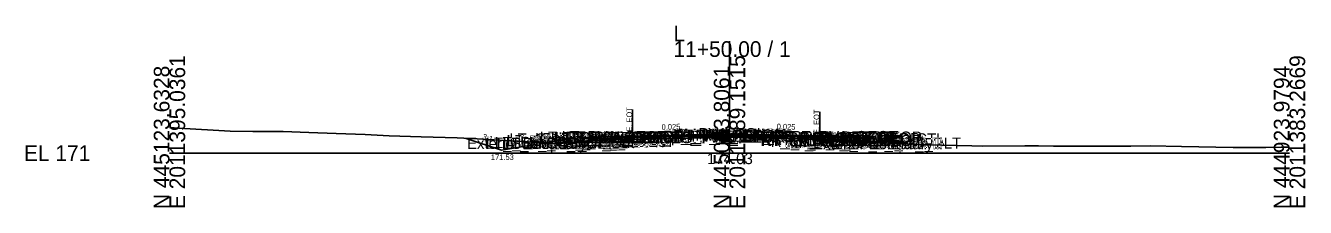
# Model space of a CAD drawing. Extents: x -26 to 4203, y -10 to 9526.
# Drawn here: x -25.7 to 202.8, y 1490.3 to 1522.8 of the extents above; entities that cross this region are included whole.
import ezdxf

# ---------------------------------------------------------------- set-up
doc = ezdxf.new("R2010")
doc.units = 0
for name, color, linetype in [('Default', 7, 'Continuous'), ('Exist CMT Pavement', 7, 'Continuous'), ('Exist Cross Section Cell', 7, 'Continuous'), ('Exist XS Center Line Elevation Label', 7, 'Continuous'), ('Exist XS Ground Line', 7, 'Continuous'), ('Prop CMT Pvmt Course 1', 7, 'Continuous'), ('Prop CMT Pvmt Course 1 Wedge', 7, 'Continuous'), ('Prop CMT Pvmt Course 2', 7, 'Continuous'), ('Prop CMT Pvmt Course 2 Wedge', 7, 'Continuous'), ('Prop CMT Pvmt Course 3', 7, 'Continuous'), ('Prop CMT Pvmt Course 3 Wedge', 7, 'Continuous'), ('Prop CMT Pvmt Surface', 7, 'Continuous'), ('Prop CMT Pvmt Surface Shoulder', 7, 'Continuous'), ('Prop CMT Pvmt Wedge Surface 1', 7, 'Continuous'), ('Prop CMT Pvmt Wedge Surface 2', 7, 'Continuous'), ('Prop CMT Pvmt Wedge Surface 3', 7, 'Continuous'), ('Prop CMT Shld Paved Course 1', 7, 'Continuous'), ('Prop CMT Shld Paved Course 2', 7, 'Continuous'), ('Prop CMT Shld Paved Course 3', 7, 'Continuous'), ('Prop CMT Slope Grass', 7, 'Continuous'), ('Prop CMT Subgrade Earthwork', 7, 'Continuous'), ('Prop XS Ditch Standard Text', 7, 'Continuous'), ('Prop XS Label Text', 7, 'Continuous'), ('Prop XS SE Text', 7, 'Continuous'), ('Prop XS Side Slope Text', 7, 'Continuous'), ('Scratch_Level_0', 7, 'Continuous')]:
    doc.layers.add(name, color=color, linetype=linetype)

msp = doc.modelspace()

# ---------------------------------------------------------------- linework, layer by layer
at = {"layer": 'Exist CMT Pavement'}
for points in [[(81.3, 1502.76), (81.49, 1502.77), (81.67, 1502.79), (81.98, 1502.8), (82.71, 1502.8), (83.5, 1502.82), (83.73, 1502.82), (85.7, 1502.83), (86.2, 1502.84), (88.42, 1502.91), (88.75, 1502.92), (89.04, 1502.92), (91.25, 1502.95), (91.39, 1502.95), (93.78, 1502.99), (93.78, 1502.99), (94.01, 1502.99), (95.28, 1503), (96.25, 1503.02), (96.4, 1503.02), (98.76, 1503.05), (100, 1503.03)], [(100, 1503.03), (100.84, 1503.01), (101.26, 1503), (103.18, 1502.94), (103.72, 1502.92), (104.28, 1502.91), (105.18, 1502.89), (105.74, 1502.87), (106.25, 1502.86), (107.92, 1502.78), (108.75, 1502.75), (109.68, 1502.71), (111.24, 1502.64), (112.63, 1502.56), (113.76, 1502.49), (115.25, 1502.42), (116.14, 1502.38)]]:
    msp.add_lwpolyline(points, dxfattribs=at)
at = {"layer": 'Exist Cross Section Cell'}
for p, q in [((100, 1500), (100, 1519.98)), ((0, 1500), (100, 1500)), ((100, 1500), (200, 1500))]:
    msp.add_line(p, q, dxfattribs=at)
at = {"layer": 'Exist XS Ground Line'}
msp.add_lwpolyline([(0, 1504.57), (1.66, 1504.47), (10.85, 1503.95), (14.89, 1503.87), (20.31, 1503.88), (24.91, 1503.66), (29.77, 1503.48), (34.93, 1503.33), (39.23, 1503.1), (44.95, 1502.93), (51.38, 1502.71), (54.97, 1502.55), (68.15, 1501.8), (69.16, 1501.74), (69.52, 1501.71), (70.83, 1501.83), (81.29, 1502.76), (81.67, 1502.79), (81.98, 1502.8), (82.71, 1502.8), (83.73, 1502.82), (85.7, 1502.83), (86.2, 1502.84), (88.42, 1502.91), (89.04, 1502.92), (91.39, 1502.95), (94.01, 1502.99), (95.28, 1503), (96.4, 1503.02), (98.76, 1503.05), (100, 1503.03), (100.84, 1503.01), (101.26, 1503), (103.18, 1502.94), (103.72, 1502.92), (104.28, 1502.91), (105.18, 1502.89), (105.74, 1502.87), (106.25, 1502.86), (107.92, 1502.78), (108.75, 1502.75), (109.68, 1502.71), (111.24, 1502.64), (112.63, 1502.56), (113.76, 1502.49), (115.25, 1502.42), (116.14, 1502.38), (117.18, 1502.31), (118.21, 1502.25), (119.08, 1502.2), (126.87, 1501.87), (135.12, 1501.51), (143.3, 1501.29), (145.14, 1501.26), (152.76, 1501.29), (155.15, 1501.29), (157.85, 1501.22), (165.17, 1501.22), (171.68, 1501.23), (175.19, 1501.32), (180.72, 1501.21), (189.97, 1501.02), (193.45, 1501.03), (195.78, 1501.03), (198.52, 1501.04), (200, 1501.05)], dxfattribs=at)
at = {"layer": 'Prop CMT Pvmt Course 1'}
for points in [[(100, 1503.47), (79.31, 1502.95)], [(79.31, 1502.95), (79.31, 1502.7)], [(79.31, 1502.7), (81.3, 1502.75)], [(82.71, 1502.91), (100, 1503.34)], [(82.71, 1502.78), (82.71, 1502.91)], [(100, 1503.22), (100, 1503.47)], [(100, 1503.47), (120.27, 1502.96)], [(100, 1503.22), (100, 1503.47)], [(100, 1503.34), (100, 1503.22), (100, 1503.22)], [(116.14, 1502.94), (100, 1503.34)], [(100, 1503.34), (100, 1503.22), (100, 1503.22)], [(116.14, 1502.81), (116.14, 1502.94)], [(120.27, 1502.71), (118.22, 1502.76)], [(120.27, 1502.96), (120.27, 1502.71)]]:
    msp.add_lwpolyline(points, dxfattribs=at)
at = {"layer": 'Prop CMT Pvmt Course 1 Wedge'}
for points in [[(100, 1503.22), (98.76, 1503.19), (96.4, 1503.13), (96.25, 1503.12), (95.28, 1503.1), (94.01, 1503.07), (93.78, 1503.06), (93.78, 1503.06), (91.39, 1503), (91.25, 1503), (89.04, 1502.94), (88.75, 1502.94), (88.42, 1502.93), (86.2, 1502.87), (85.7, 1502.86), (84.28, 1502.82), (83.73, 1502.82), (83.5, 1502.82), (82.71, 1502.8), (81.98, 1502.8), (81.67, 1502.79), (81.49, 1502.77), (81.3, 1502.76)], [(82.71, 1502.91), (82.71, 1502.91), (83.5, 1502.93), (83.73, 1502.93), (85.7, 1502.98), (86.2, 1503), (88.42, 1503.05), (88.75, 1503.06), (89.04, 1503.07), (91.25, 1503.12), (91.39, 1503.13), (93.78, 1503.19), (93.78, 1503.19), (94.01, 1503.19), (95.28, 1503.22), (96.25, 1503.25), (96.4, 1503.25), (98.76, 1503.31), (100, 1503.34)], [(82.71, 1502.8), (82.71, 1502.91)], [(100, 1503.22), (100, 1503.34)], [(100, 1503.34), (100, 1503.22)], [(100, 1503.34), (100.84, 1503.32), (101.26, 1503.31), (103.18, 1503.26), (103.72, 1503.25), (104.28, 1503.23), (105.18, 1503.21), (105.74, 1503.2), (106.25, 1503.19), (107.92, 1503.14), (108.75, 1503.12), (109.68, 1503.1), (111.24, 1503.06), (112.63, 1503.03), (113.76, 1503), (115.25, 1502.96), (116.14, 1502.94)], [(118.22, 1502.76), (118.21, 1502.76), (117.18, 1502.79), (116.89, 1502.79), (116.23, 1502.81), (116.14, 1502.81), (115.25, 1502.84), (113.76, 1502.87), (112.63, 1502.9), (111.24, 1502.94), (109.68, 1502.97), (108.75, 1503), (107.92, 1503.02), (106.25, 1503.06), (105.74, 1503.07), (105.18, 1503.09), (104.28, 1503.11), (103.72, 1503.12), (103.18, 1503.14), (101.26, 1503.19), (100.84, 1503.2), (100, 1503.22)], [(116.14, 1502.94), (116.14, 1502.81)]]:
    msp.add_lwpolyline(points, dxfattribs=at)
at = {"layer": 'Prop CMT Pvmt Course 2'}
for points in [[(82.71, 1502.78), (79.31, 1502.7)], [(79.31, 1502.7), (79.31, 1502.37)], [(79.31, 1502.37), (81.3, 1502.42)], [(82.71, 1502.45), (82.71, 1502.78)], [(116.14, 1502.48), (116.14, 1502.81)], [(118.22, 1502.76), (120.27, 1502.71)], [(120.27, 1502.38), (118.22, 1502.43)], [(120.27, 1502.71), (120.27, 1502.38)]]:
    msp.add_lwpolyline(points, dxfattribs=at)
at = {"layer": 'Prop CMT Pvmt Course 2 Wedge'}
for points in [[(100, 1503.03), (98.76, 1503.05), (96.4, 1503.02), (96.25, 1503.02), (95.28, 1503), (94.01, 1502.99), (93.78, 1502.99), (93.78, 1502.99), (91.39, 1502.95), (91.25, 1502.95), (89.04, 1502.92), (88.75, 1502.92), (88.42, 1502.91), (86.2, 1502.84), (85.7, 1502.83), (84.29, 1502.82)], [(84.29, 1502.82), (85.7, 1502.86)], [(85.7, 1502.86), (86.2, 1502.87), (88.42, 1502.93), (88.75, 1502.94), (89.04, 1502.94), (91.25, 1503), (91.39, 1503), (93.78, 1503.06), (93.78, 1503.06), (94.01, 1503.07), (95.28, 1503.1), (96.25, 1503.12), (96.4, 1503.13), (98.76, 1503.18), (100, 1503.22)], [(100, 1503.22), (100.84, 1503.19), (101.26, 1503.18), (103.18, 1503.14), (103.72, 1503.12), (104.28, 1503.11), (105.18, 1503.09), (105.74, 1503.07), (106.25, 1503.06), (107.92, 1503.02), (108.75, 1503), (109.68, 1502.97), (111.24, 1502.94), (112.63, 1502.9), (113.76, 1502.87), (115.25, 1502.84), (116.14, 1502.81), (116.23, 1502.81), (116.89, 1502.79), (117.18, 1502.79), (118.21, 1502.76), (118.22, 1502.76)], [(100, 1503.03), (100, 1503.22)], [(100, 1503.22), (100, 1503.03)], [(116.14, 1502.48), (115.25, 1502.5), (113.76, 1502.54), (112.63, 1502.57), (112.3, 1502.58), (111.24, 1502.64), (109.68, 1502.71), (108.75, 1502.75), (107.92, 1502.78), (106.25, 1502.86), (105.74, 1502.87), (105.18, 1502.89), (104.28, 1502.91), (103.72, 1502.92), (103.18, 1502.94), (101.26, 1503), (100.84, 1503.01), (100, 1503.03)], [(116.14, 1502.81), (116.14, 1502.48)]]:
    msp.add_lwpolyline(points, dxfattribs=at)
at = {"layer": 'Prop CMT Pvmt Course 3'}
for points in [[(82.71, 1502.45), (79.31, 1502.37)], [(79.31, 1502.37), (79.31, 1502.03)], [(79.31, 1502.03), (82.71, 1502.12)], [(82.71, 1502.12), (82.71, 1502.45)], [(116.14, 1502.48), (120.27, 1502.38)], [(116.14, 1502.15), (116.14, 1502.48)], [(120.27, 1502.04), (116.14, 1502.15)], [(120.27, 1502.38), (120.27, 1502.04)]]:
    msp.add_lwpolyline(points, dxfattribs=at)
at = {"layer": 'Prop CMT Pvmt Course 3 Wedge'}
for points in [[(118.22, 1502.25), (118.21, 1502.25), (117.18, 1502.31), (116.89, 1502.33), (116.23, 1502.37), (116.14, 1502.38), (115.25, 1502.42), (113.76, 1502.49), (112.63, 1502.56), (112.29, 1502.58)], [(112.29, 1502.58), (112.63, 1502.57)], [(112.63, 1502.57), (113.76, 1502.54), (115.25, 1502.5), (116.14, 1502.48), (116.14, 1502.48)], [(116.14, 1502.48), (116.14, 1502.3)]]:
    msp.add_lwpolyline(points, dxfattribs=at)
at = {"layer": 'Prop CMT Pvmt Surface'}
for points in [[(100, 1503.47), (79.31, 1502.95)], [(100, 1503.47), (120.27, 1502.96)]]:
    msp.add_lwpolyline(points, dxfattribs=at)
at = {"layer": 'Prop CMT Pvmt Surface Shoulder'}
for points in [[(79.31, 1502.95), (75.3, 1502.85)], [(120.27, 1502.96), (124.27, 1502.86)]]:
    msp.add_lwpolyline(points, dxfattribs=at)
at = {"layer": 'Prop CMT Pvmt Wedge Surface 1'}
for points in [[(79.31, 1502.7), (79.31, 1502.95)], [(81.3, 1502.75), (79.31, 1502.7)], [(100, 1503.34), (82.71, 1502.91)], [(82.71, 1502.91), (82.71, 1502.78)], [(100, 1503.34), (116.14, 1502.94)], [(116.14, 1502.94), (116.14, 1502.81)], [(118.22, 1502.76), (120.27, 1502.71)], [(120.27, 1502.71), (120.27, 1502.96)]]:
    msp.add_lwpolyline(points, dxfattribs=at)
at = {"layer": 'Prop CMT Pvmt Wedge Surface 2'}
for points in [[(79.31, 1502.7), (79.31, 1502.95)], [(100, 1503.22), (82.71, 1502.78)], [(100, 1503.22), (120.27, 1502.71)], [(120.27, 1502.71), (120.27, 1502.96)]]:
    msp.add_lwpolyline(points, dxfattribs=at)
at = {"layer": 'Prop CMT Pvmt Wedge Surface 3'}
for points in [[(79.31, 1502.37), (79.31, 1502.95)], [(100, 1502.88), (82.71, 1502.45)], [(100, 1502.88), (116.14, 1502.48)], [(120.27, 1502.38), (120.27, 1502.96)]]:
    msp.add_lwpolyline(points, dxfattribs=at)
at = {"layer": 'Prop CMT Shld Paved Course 1'}
for points in [[(79.31, 1502.95), (75.3, 1502.85), (75.05, 1502.59)], [(75.05, 1502.59), (79.31, 1502.7)], [(79.31, 1502.7), (79.31, 1502.95)], [(120.27, 1502.96), (124.27, 1502.86), (124.53, 1502.6)], [(120.27, 1502.71), (120.27, 1502.96)], [(124.53, 1502.6), (120.27, 1502.71)]]:
    msp.add_lwpolyline(points, dxfattribs=at)
at = {"layer": 'Prop CMT Shld Paved Course 2'}
for points in [[(79.31, 1502.7), (75.05, 1502.59), (74.71, 1502.25)], [(74.71, 1502.25), (79.31, 1502.37)], [(79.31, 1502.37), (79.31, 1502.7)], [(120.27, 1502.71), (124.53, 1502.6), (124.87, 1502.26)], [(120.27, 1502.38), (120.27, 1502.71)], [(124.87, 1502.26), (120.27, 1502.38)]]:
    msp.add_lwpolyline(points, dxfattribs=at)
at = {"layer": 'Prop CMT Shld Paved Course 3'}
for points in [[(79.31, 1502.37), (75.21, 1502.26), (74.71, 1502.25), (74.36, 1501.91)], [(74.36, 1501.91), (79.31, 1502.03)], [(79.31, 1502.03), (79.31, 1502.37)], [(120.27, 1502.38), (124.37, 1502.27), (124.87, 1502.26), (125.21, 1501.92)], [(120.27, 1502.04), (120.27, 1502.38)], [(125.21, 1501.92), (120.27, 1502.04)]]:
    msp.add_lwpolyline(points, dxfattribs=at)
at = {"layer": 'Prop CMT Slope Grass'}
for points in [[(75.3, 1502.85), (71.31, 1502.53), (59.31, 1500.53), (52.97, 1502.64)], [(124.27, 1502.86), (128.27, 1502.54), (130.79, 1501.7)]]:
    msp.add_lwpolyline(points, dxfattribs=at)
at = {"layer": 'Prop CMT Subgrade Earthwork'}
for points in [[(73.86, 1501.9), (66.39, 1501.71)], [(79.31, 1502.03), (73.86, 1501.9)], [(82.71, 1502.12), (79.31, 1502.03)], [(82.71, 1502.12), (82.71, 1502.8)], [(116.14, 1502.15), (116.14, 1502.38)], [(116.14, 1502.15), (120.27, 1502.04)], [(120.27, 1502.04), (125.71, 1501.91)], [(125.71, 1501.91), (130.53, 1501.79)]]:
    msp.add_lwpolyline(points, dxfattribs=at)
at = {"layer": 'Prop XS Label Text'}
for p, q in [((82.71, 1507.8), (82.71, 1502.8)), ((116.14, 1507.38), (116.14, 1502.38))]:
    msp.add_line(p, q, dxfattribs=at)

# ---------------------------------------------------------------- texts
at = {"layer": 'Default'}
msp.add_text('-', height=0.0001, dxfattribs=at).set_placement((0, 1500))
at = {"layer": 'Exist Cross Section Cell'}
for s, p in [('L', (90, 1519.98)), ('11+50.00 / 1', (90, 1517.18)), ('EL 171', (-26, 1498.6))]:
    msp.add_text(s, height=2.8, dxfattribs=at).set_placement(p)
for s, p in [('N 445123.6328', (0, 1490)), ('E 2011395.0361', (2.8, 1490)), ('N 445023.8061', (100, 1490)), ('E 2011389.1515', (102.8, 1490)), ('N 444923.9794', (200, 1490)), ('E 2011383.2669', (202.8, 1490))]:
    msp.add_text(s, height=2.8, rotation=90, dxfattribs=at).set_placement(p)
at = {"layer": 'Exist XS Center Line Elevation Label'}
msp.add_text('174.03', height=2, dxfattribs=at).set_placement((95.99, 1498.03))
at = {"layer": 'Prop XS Ditch Standard Text'}
msp.add_text('171.53', height=1, dxfattribs=at).set_placement((57.4, 1498.78))
at = {"layer": 'Prop XS Label Text'}
for p in [(82.61, 1503.83), (116.04, 1503.4)]:
    msp.add_text('E. EOT', height=1, rotation=90, dxfattribs=at).set_placement(p)
at = {"layer": 'Prop XS SE Text'}
for rotation, p in [(1.434, (87.89, 1504.16)), (358.567, (108.42, 1504.26))]:
    msp.add_text('0.025', height=1, rotation=rotation, dxfattribs=at).set_placement(p)
at = {"layer": 'Prop XS Side Slope Text'}
for s, rotation, p in [('3:1', 341.5741, (129.01, 1503.08)), ('3:1', 341.5613, (55.79, 1502.55)), ('6:1', 9.4625, (64.4, 1502.14))]:
    msp.add_text(s, height=1, rotation=rotation, dxfattribs=at).set_placement(p)
at = {"layer": 'Scratch_Level_0'}
for s, p in [('LT_PS1_OEOP', (66.11, 1501.85)), ('LT_Sub Tie Out', (68.64, 1501.76)), ('LT_PV_OEEOP_EG', (68.84, 1501.76)), ('LT_PV1_OEOT', (70.05, 1501.95)), ('LT_PV2_OEEOP', (70.61, 1501.75)), ('LT_PV1_OEEOP', (71.17, 1501.87)), ('RT_PV_IEEOP_EG', (88.14, 1502.03)), ('LT_PV_IEEOP_EG', (88.19, 1502.03)), ('RT_PV2_IEEOP', (89.91, 1502.22)), ('RT_PV3_IEEOP', (89.91, 1501.88)), ('LT_PV2_IEEOP', (89.95, 1502.22)), ('LT_PV3_IEEOP', (89.95, 1501.88)), ('RT_PV1_IEEOP', (90.47, 1502.34)), ('LT_PV1_IEEOP', (90.52, 1502.34)), ('PV2_PGL', (93.91, 1502.22)), ('PV1_PGL', (94.47, 1502.47)), ('RT_PV2_OEEOP', (107.48, 1501.76)), ('RT_PV1_OEEOP', (108.04, 1501.89)), ('RT_PV1_OEOT', (110.96, 1501.96)), ('RT_PS1_OEOP', (115.03, 1501.86)), ('Exterior Boundary', (53.12, 1500.75)), ('LT_Sub_OSS_DLT', (56.45, 1500.78)), ('LT_Sub_OSS_DLT', (56.45, 1500.78)), ('LT_Sub_Trench_Out', (58.07, 1500.9)), ('LT_Slope_Fill', (59.5, 1500.75)), ('LT_PS3_Shelf_Out', (60.19, 1501.24)), ('LT_GS_OS_CTL', (60.68, 1501.53)), ('LT_PS3_OEOP', (64.94, 1501.25)), ('LT_PS2_OEOP', (65.28, 1501.59)), ('LT_Sub_OEOT', (69.39, 1501.03)), ('LT_PV2_OEOT', (69.48, 1501.7)), ('LT_PV3_OEOT', (69.48, 1501.37)), ('LT_Sub_OEEOP', (70.51, 1501.08)), ('LT_PV3_OEEOP', (70.61, 1501.42)), ('RT_Sub Tie Out', (105.51, 1501.25)), ('RT_PV_OEEOP_EG', (105.71, 1501.25)), ('RT_Sub_OEEOP', (107.38, 1501.09)), ('RT_PV3_OEEOP', (107.48, 1501.43)), ('RT_Sub_Trench_Out', (109.87, 1500.91)), ('RT_Sub_OEOT', (110.3, 1501.04)), ('RT_PV2_OEOT', (110.39, 1501.71)), ('RT_PV3_OEOT', (110.39, 1501.38)), ('RT_PS3_Shelf_Out', (111.31, 1501.25)), ('RT_PS2_OEOP', (114.72, 1501.6)), ('Exterior Boundary', (114.93, 1500.7)), ('RT_PS3_OEOP', (115.06, 1501.26)), ('RT_GS_OS_CTL', (117.59, 1501.54)), ('RT_Sub_OSS_DLT', (117.88, 1500.79)), ('RT_Slope_Fill', (121.26, 1500.7))]:
    msp.add_text(s, height=2, dxfattribs=at).set_placement(p)

doc.saveas('drawing.dxf')
